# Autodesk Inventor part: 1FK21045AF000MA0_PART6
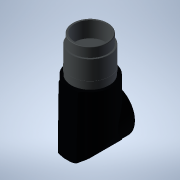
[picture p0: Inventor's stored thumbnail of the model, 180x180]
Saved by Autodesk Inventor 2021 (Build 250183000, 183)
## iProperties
Created: 2025-04
Part Number: 1FK21045AF000MA0_PART6
Material: Generic
Catalog Web Link: www.3dfindit.com
Description: -Servo synchronous motor
Document SubType Name: Modeling
Designer: psAdmin
Mass: 11.0817 g
Surface Area: 35.706 cm^2
Volume: 11.0817 cm^3
Density: 1 g/cm^3
Appearance: PSOLRGB-176-176-176
Category: PARTsolutions
Title: 1FK21045AF000MA0_PART6
Author: Cadenas PARTsolutions
Comments: Servo synchronous motor
Sending System: PARTsolutions
Preprocessor: ST-DEVELOPER v19.3
PSOL_IDENT_0: {$CADENAS_DATA/23d-libs/siemens_ag/_cat_/8b/0a/1fk21045af000ma0.prj},213 {VTYP=3D},{NB=1FK21045AF000
PSOL_IDENT_1: MA0_PART6},{LINA=1FK21045AF000MA0_PART6},{NN=1FK21045AF000MA0_PART6},{NOPRJ=TRUE},{DATE=19.08.2025 1
PSOL_IDENT_2: 4:00:48},{GEOMDATE=30.07.2025 02:00:28},{VERSION=},{LINEID=10},{WBVAR=},{WBNUMERIC=}  {NB=1FK21045AF
PSOL_IDENT_3: 000MA0_PART6},{LINA=1FK21045AF000MA0_PART6},{KT=DUMMY},{PREVIEW=../../../_pool_/a9/69/p_d211_xx_0081
PSOL_IDENT_4: 8j.png},{DESCSHORT=SIMOTICS S-1FK2 HD, SINAMICS S210 3AC 400V-480V, 2.4 Nm, 3000 rpm},{DESCLONG=SIMO
PSOL_IDENT_5: TICS S-1FK2 HD servo motor M0=2.4 Nm; PN = 0.75 kW at nN=3000 rpm (380-480 V); PN = 0.375 kW at nN=1
PSOL_IDENT_6: 500 rpm (200-240 V); degree of protection IP64; cylindrical shaft D19x40mm; absolute encoder 22-bit
PSOL_IDENT_7: + 12-bit multiturn (encoder AM22DQC); with OCC interface; plug size M17, rotatable; SIMOTICS S-1FK2
PSOL_IDENT_8: servomotorfor a wide range of uses in industrial environments. SIMOTICS S‑1FK2 servomotors are compa
PSOL_IDENT_9: ct synchronous motors with a high dynamic performance that set themselves apart as a result of their
PSOL_IDENT_10: high power density, degree of protection and overload capability. The motors are available in two v
PSOL_IDENT_11: ariants: as High Dynamic variant (highest dynamic performance as a result of the low intrinsic momen
PSOL_IDENT_12: t of inertia for applications demanding a high dynamic performance with low moved masses) - and as C
PSOL_IDENT_13: ompact variant (precise and stable closed-loop control for medium up to large moved masses as a resu
PSOL_IDENT_14: lt of a medium intrinsic moment of inertia). SIMOTICSS‑1FK2 servomotors fully exploit their strength
PSOL_IDENT_15: s in a system with the SINAMICSS210 frequency converter and simple connection using the one cable co
PSOL_IDENT_16: nnection (OCC). Advantages include the short control and positioning times, fast and precise correct
PSOL_IDENT_17: ion of disturbing quantities as well as stable control with a high dynamic performance. The servo mo
PSOL_IDENT_18: tors can be configured to address a wide range of requirements. For example with and without holding
PSOL_IDENT_19: brake, IP64 or IP65 degree of protection, singleturn or multiturn absolute encoders - to name just
PSOL_IDENT_20: a few. Further, the servomotors are available in different shaft heights extending from 20 to 100. A
PSOL_IDENT_21: shaft sealing ring is available to achieve an IP65 degree of protection and for subsequent mounting
PSOL_IDENT_22: at the motor or as spare part. SIMOTICS - the optimum motor for each and every motion control appli
PSOL_IDENT_23: cation.},{INTNO=195125050112},{SUPPLIERALTNO=1FK2104-5AF00-0MA0},{MANUID=1FK21045AF000MA0},{MANUNAME=
PSOL_IDENT_24: Siemens},{MANUTYPEDESC=Synchronous motor 1FK2-HD 2.4 NM},{AAU732=SIMOTICS},{AAO057=S-1FK2},{AAU734=S
PSOL_IDENT_25: IMOTICS S-1FK2 HD servo motor M0=2.4 Nm; PN = 0.75 kW at nN=3000 rpm (380-480 V); PN = 0.375 kW at n
PSOL_IDENT_26: N=1500 rpm (200-240 V); degree of protection IP64; cylindrical shaft D19x40mm; absolute encoder 22-b
PSOL_IDENT_27: it + 12-bit multiturn (encoder AM22DQC); with OCC interface; plug size M17, rotatable;},{AAW338=Sync
PSOL_IDENT_28: hronous motor 1FK2-HD 2.4 NM},{AAO742=SIMOTICS},{AAO663=4042948692912},{NOCUPEROU=1},{PRICEQUANTITY=
PSOL_IDENT_29: 1},{QUANTITYMIN=1},{QUANTITYINT=1},{CTN=85015100},{COO=DE},{AAO676=1FK2104-5AF00-0MA0},{AAO677=Sieme
PSOL_IDENT_30: ns AG},{ORDERUNIT=C62},{CONTENTUNIT=C62}
NB: 1FK21045AF000MA0_PART6
NT: Servo synchronous motor
NBSYN: $MANUID._PART6
LINA: 1FK21045AF000MA0_PART6
CATALOG: SIEMENS
PREVIEW: ../../../_pool_/a9/69/p_d211_xx_00818j.png
DESCSHORT: SIMOTICS S-1FK2 HD, SINAMICS S210 3AC 400V-480V, 2.4 Nm, 3000 rpm
DESCLONG: SIMOTICS S-1FK2 HD servo motor M0=2.4 Nm; PN = 0.75 kW at nN=3000 rpm (380-480 V); PN = 0.375 kW at nN=1500 rpm (200-240 V); degree of protection IP64; cylindri
INTNO: 195125050112
SUPPLIERALTNO: 1FK2104-5AF00-0MA0
MANUID: 1FK21045AF000MA0
MANUNAME: Siemens
MANUTYPEDESC: Synchronous motor 1FK2-HD 2.4 NM
AAU732: SIMOTICS
AAO057: S-1FK2
AAU734: SIMOTICS S-1FK2 HD servo motor M0=2.4 Nm; PN = 0.75 kW at nN=3000 rpm (380-480 V); PN = 0.375 kW at nN=1500 rpm (200-240 V); degree of protection IP64; cylindri
AAW338: Synchronous motor 1FK2-HD 2.4 NM
AAO742: SIMOTICS
AAO663: 4042948692912.0
NOCUPEROU: 1
PRICEQUANTITY: 1
QUANTITYMIN: 1
QUANTITYINT: 1
CTN: 85015100
COO: DE
ARTICLENO: 1FK21045AF000MA0_PART6
BOMINFO: 1FK21045AF000MA0_PART6
CREATOR: CADENAS GmbH
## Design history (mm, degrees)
feature "2025_04_17_15_40_42_0734"
body "Solid1"
